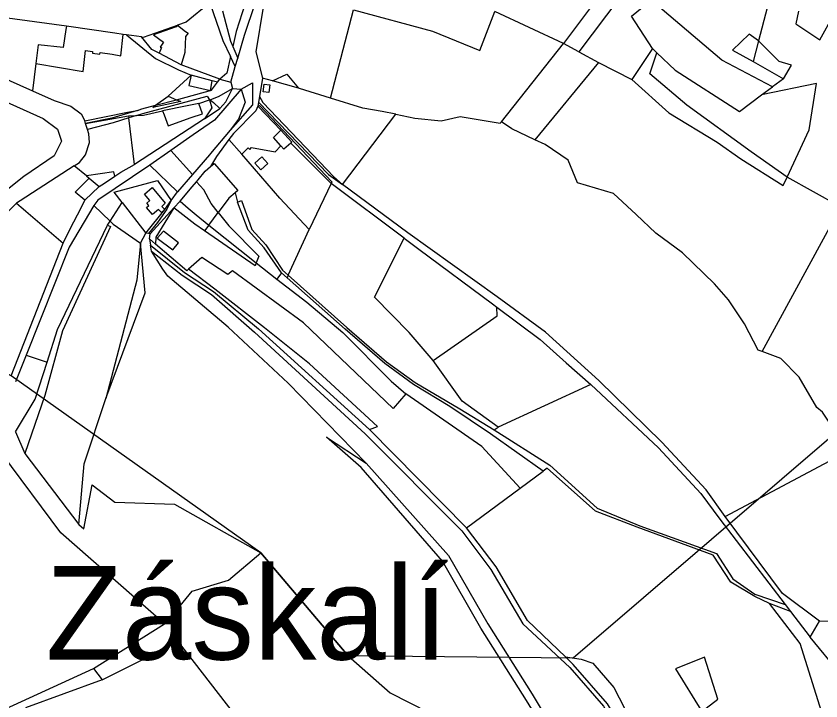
# Model space of a CAD drawing. Extents: x -689422 to -684666, y -987725 to -982160.
# Drawn here: x -687230 to -686713, y -983777 to -983338 of the extents above; entities that cross this region are included whole.
import ezdxf

# ---------------------------------------------------------------- set-up
doc = ezdxf.new("R2010")
doc.units = 0
for name, color, linetype in [('KN_Hranice_katastrální území_popis', 7, 'Continuous'), ('KN_hranice_parcel', 7, 'Continuous'), ('Migracne vyznamne uzemi', 7, 'Continuous')]:
    doc.layers.add(name, color=color, linetype=linetype)

msp = doc.modelspace()

# ---------------------------------------------------------------- linework, layer by layer
at = {"layer": 'KN_hranice_parcel'}
for p, q in [((-686834.38, -983315.81), (-686868.04, -983360.6)), ((-687105.15, -983329.15), (-687120.26, -983341.45)), ((-686746.94, -983332.27), (-686752.52, -983353.42)), ((-687027.62, -983390.28), (-687012.88, -983333.6)), ((-686877.9, -983355.22), (-686921.98, -983334.62)), ((-687120.26, -983341.45), (-687125.93, -983343.43)), ((-687158.66, -983349.73), (-687160.79, -983349.39)), ((-687149.12, -983350.91), (-687158.66, -983349.73)), ((-687087.21, -983364.63), (-687082.94, -983349.91)), ((-686752.52, -983353.42), (-686756.06, -983366.84)), ((-687090.42, -983357.15), (-687087.21, -983364.63)), ((-686917.81, -983405.46), (-686877.9, -983355.22)), ((-686868.04, -983360.6), (-686877.9, -983355.22)), ((-686820.77, -983358.38), (-686834.03, -983378.26)), ((-686817.92, -983361.09), (-686820.77, -983358.38)), ((-687184.91, -983359.69), (-687180.43, -983360.31)), ((-687123.48, -983368.86), (-687137.75, -983361.49)), ((-687088.78, -983370.02), (-687091.87, -983363.57)), ((-686868.04, -983360.6), (-686855.49, -983367.29)), ((-686817.92, -983361.09), (-686806.05, -983372.37)), ((-687259.05, -983367.72), (-687219.14, -983385.58)), ((-687216.87, -983367.98), (-687219.14, -983385.58)), ((-687098.75, -983378.01), (-687123.48, -983368.86)), ((-687088.78, -983370.02), (-687087.21, -983364.63)), ((-686855.49, -983367.29), (-686896.24, -983416.98)), ((-686855.49, -983367.29), (-686834.03, -983378.26)), ((-686756.06, -983366.84), (-686736.63, -983377.83)), ((-687125.16, -983372.16), (-687117.17, -983375.5)), ((-687091.67, -983379.99), (-687088.78, -983370.02)), ((-686806.05, -983372.37), (-686764.84, -983398.77)), ((-686736.63, -983377.83), (-686731.36, -983369.11)), ((-687117.17, -983375.5), (-687131.89, -983389.11)), ((-687103.58, -983379.2), (-687117.17, -983375.5)), ((-687100.26, -983380.11), (-687103.58, -983379.2)), ((-687100.26, -983380.11), (-687098.75, -983378.01)), ((-687098.75, -983378.01), (-687091.67, -983379.99)), ((-687071.32, -983377.38), (-687073.27, -983389.15)), ((-687064.95, -983379.22), (-687071.32, -983377.38)), ((-687048.24, -983383.9), (-687064.95, -983379.22)), ((-686736.63, -983377.83), (-686743.52, -983382.94)), ((-687091.67, -983379.99), (-687090.67, -983384.03)), ((-687090.67, -983384.03), (-687085.04, -983384.63)), ((-687047.51, -983384.13), (-687048.24, -983383.9)), ((-687027.62, -983390.28), (-687047.51, -983384.13)), ((-686750.58, -983388.18), (-686743.52, -983382.94)), ((-687219.14, -983385.58), (-687205.11, -983391.86)), ((-687140, -983394.9), (-687131.89, -983389.11)), ((-687131.89, -983389.11), (-687126.53, -983391.29)), ((-687073.27, -983389.15), (-687073.91, -983392.87)), ((-686764.84, -983398.77), (-686750.58, -983388.18)), ((-687148.74, -983397.24), (-687140, -983394.9)), ((-687123.67, -983392.46), (-687141.86, -983396.23)), ((-687141.86, -983396.23), (-687140, -983394.9)), ((-687140, -983394.9), (-687126.53, -983391.29)), ((-687126.53, -983391.29), (-687123.67, -983392.46)), ((-687112.26, -983393.83), (-687105.34, -983391.45)), ((-687105.34, -983391.45), (-687104.97, -983391.3)), ((-687077.62, -983394.49), (-687092.1, -983410.86)), ((-687073.91, -983392.87), (-687074.38, -983395.35)), ((-687006.85, -983396.7), (-687027.62, -983390.28)), ((-687151.69, -983398.13), (-687148.74, -983397.24)), ((-687108.62, -983403.55), (-687098.65, -983396.99)), ((-687059.42, -983410.87), (-687074.38, -983395.35)), ((-687184.91, -983406.49), (-687185.45, -983404.81)), ((-687184.91, -983406.49), (-687157.31, -983401.66)), ((-687157.31, -983401.66), (-687152.2, -983401.4)), ((-687157.31, -983401.66), (-687157.15, -983402.94)), ((-687152.2, -983401.4), (-687157.15, -983402.94)), ((-687153.51, -983432.98), (-687157.15, -983402.94)), ((-687108.62, -983403.55), (-687153.51, -983432.98)), ((-687019.92, -983445.77), (-686985.68, -983400.67)), ((-687183.75, -983410.33), (-687184.91, -983406.49)), ((-687089.96, -983412.96), (-687092.89, -983416.93)), ((-687092.89, -983416.93), (-687100.86, -983427.71)), ((-687084.56, -983426.38), (-687092.89, -983416.93)), ((-687027.27, -983445.21), (-687053.13, -983419.15)), ((-687130.14, -983423.89), (-687143.69, -983433.36)), ((-687116.37, -983439.4), (-687130.14, -983423.89)), ((-687084.56, -983426.38), (-687080.43, -983422.3)), ((-687100.86, -983427.71), (-687104.65, -983434.16)), ((-687192.2, -983433.83), (-687227, -983456.25)), ((-687192.2, -983433.83), (-687188.77, -983431.62)), ((-687184.47, -983440.25), (-687192.2, -983433.83)), ((-687162.32, -983437.89), (-687153.51, -983432.98)), ((-687125.91, -983450.39), (-687143.69, -983433.36)), ((-687184.47, -983440.25), (-687182.65, -983441.76)), ((-687172.88, -983444.91), (-687166.19, -983440.46)), ((-687166.19, -983440.46), (-687162.32, -983437.89)), ((-687116.37, -983439.4), (-687125.91, -983450.39)), ((-686699.86, -983460.25), (-686734.09, -983441.15)), ((-687182.65, -983441.76), (-687176.21, -983447.12)), ((-687176.21, -983447.12), (-687172.88, -983444.91)), ((-687027.27, -983445.21), (-687041.25, -983474.64)), ((-686980.35, -983480.19), (-687027.27, -983445.21)), ((-687185.36, -983455.81), (-687176.21, -983447.12)), ((-687129.91, -983455.95), (-687125.91, -983450.39)), ((-687088.86, -983451.06), (-687087.37, -983457.19)), ((-687227, -983456.25), (-687229.44, -983457.82)), ((-687128.26, -983460.84), (-687124.26, -983456.5)), ((-687229.44, -983457.82), (-687199.43, -983483.54)), ((-687179.6, -983459.23), (-687195.51, -983485.99)), ((-687179.6, -983459.23), (-687169.27, -983469.31)), ((-687169.27, -983469.31), (-687161.51, -983457.27)), ((-687161.51, -983457.27), (-687146.2, -983476.98)), ((-687128.26, -983460.84), (-687143.51, -983477.37)), ((-686750.35, -983553.02), (-686699.86, -983460.25)), ((-687105.73, -983471.87), (-687099.7, -983463.74)), ((-687170.91, -983471.86), (-687169.27, -983469.31)), ((-687169.27, -983469.31), (-687167.33, -983471.2)), ((-687167.33, -983471.2), (-687149.64, -983483.42)), ((-687105.73, -983471.87), (-687108.46, -983475.55)), ((-687105.73, -983471.87), (-687075.26, -983496.07)), ((-687149.64, -983483.42), (-687146.2, -983476.98)), ((-687144.55, -983477.22), (-687146.2, -983476.98)), ((-687143.51, -983477.37), (-687144.55, -983477.22)), ((-687143.95, -983480.62), (-687143.51, -983477.37)), ((-687054.77, -983504.1), (-687041.25, -983474.64)), ((-687140.03, -983484.01), (-687143.95, -983480.62)), ((-687143.95, -983480.62), (-687143.28, -983484.66)), ((-687232.68, -983568.74), (-687199.43, -983483.54)), ((-687195.51, -983485.99), (-687223.08, -983555.33)), ((-687142.61, -983488.68), (-687143.28, -983484.66)), ((-687075.26, -983496.07), (-687062.02, -983506.59)), ((-687059.08, -983502.58), (-687062.02, -983506.59)), ((-687055.52, -983505.74), (-687059.08, -983502.58)), ((-687054.77, -983504.1), (-687055.52, -983505.74)), ((-687018.25, -983538.77), (-687055.52, -983505.74)), ((-686750.35, -983553.02), (-686752.86, -983552.09)), ((-686738.28, -983557.47), (-686750.35, -983553.02)), ((-687223.08, -983555.33), (-687229.92, -983572.53)), ((-687223.08, -983555.33), (-687209.69, -983559.88)), ((-686860.32, -983574.25), (-686919.86, -983601.61)), ((-686922.53, -983603.39), (-686919.86, -983601.61)), ((-687229.92, -983604.69), (-687224.07, -983618.51)), ((-687002.49, -983603.13), (-686940.27, -983666.28)), ((-687224.07, -983618.51), (-687189.26, -983664.07)), ((-686774.11, -983658.97), (-686695.89, -983617.44)), ((-686905.75, -983640.73), (-686891.05, -983629.85)), ((-686940.27, -983666.28), (-686905.75, -983640.73)), ((-686732.12, -983719.97), (-686745.64, -983714.86)), ((-686735.51, -983715.55), (-686732.12, -983719.97)), ((-686732.12, -983719.97), (-686719.4, -983736.59)), ((-686876.67, -983749.23), (-686900.92, -983725.78)), ((-686713.37, -983726.29), (-686689.06, -983725.26)), ((-687179.87, -983756.72), (-687134.27, -983727.91)), ((-686719.4, -983736.59), (-686713.37, -983726.29)), ((-686647.66, -983823.83), (-686719.4, -983736.59)), ((-686871.6, -983754.13), (-686876.67, -983749.23)), ((-687245.86, -983786.78), (-687179.87, -983756.72)), ((-687179.87, -983756.72), (-687174.23, -983763.85)), ((-687174.23, -983763.85), (-687223.64, -983781.88))]:
    msp.add_line(p, q, dxfattribs=at)
for points in [[(-686871.38, -983281.58), (-686849.04, -983316.51), (-686877.9, -983355.22)], [(-687082.84, -983298.11), (-687082.36, -983329.58), (-687088.24, -983347.5), (-687090.42, -983357.15)], [(-687082.94, -983349.91), (-687076, -983329.47), (-687068.61, -983307.73), (-687064.66, -983300.02)], [(-687056.83, -983304.26), (-687070.68, -983330.55), (-687075.63, -983360.56), (-687071.32, -983377.38)], [(-686820.77, -983358.38), (-686834.14, -983337.72), (-686821.52, -983327.31)], [(-686743.52, -983382.94), (-686776.1, -983365.8), (-686821.52, -983327.31)], [(-687105.15, -983329.15), (-687096.85, -983353.17), (-687091.87, -983363.57)], [(-687197.28, -983344.02), (-687243.35, -983337.78), (-687256.96, -983337.75), (-687261.92, -983338.99), (-687267.57, -983342.89), (-687271.39, -983350.68), (-687270.61, -983356.98), (-687259.05, -983367.72)], [(-687096.9, -983334.14), (-687091.93, -983353.62), (-687090.42, -983357.15)], [(-687012.88, -983333.6), (-686962.16, -983347.24), (-686931.69, -983359.64), (-686921.98, -983334.62)], [(-686726.98, -983334.46), (-686728.61, -983342.58), (-686713.15, -983352.94), (-686704.5, -983336.92)], [(-687197.28, -983344.02), (-687197.67, -983346.12), (-687199.29, -983357.71)], [(-687160.79, -983349.39), (-687166.08, -983348.54), (-687197.28, -983344.02)], [(-687149.12, -983350.91), (-687147.83, -983351.07), (-687125.93, -983343.43)], [(-687125.93, -983343.43), (-687126.7, -983344.38), (-687134.76, -983347.23), (-687141.24, -983349.58), (-687134.81, -983354.37), (-687136.95, -983357.5), (-687136.24, -983357.83), (-687137.75, -983361.49)], [(-687125.93, -983343.43), (-687120.72, -983347.47), (-687119.15, -983348.57), (-687120.81, -983350.65), (-687121.11, -983361.01), (-687123.48, -983368.86)], [(-687180.43, -983360.31), (-687180.56, -983361.3), (-687175.81, -983361.95), (-687175.68, -983360.96), (-687167.91, -983362.03), (-687162.41, -983363.02), (-687160.79, -983349.39)], [(-687158.66, -983349.73), (-687140.02, -983364.77), (-687125.16, -983372.16)], [(-687137.75, -983361.49), (-687142.46, -983359.06), (-687149.12, -983350.91)], [(-686752.52, -983353.42), (-686758.56, -983349.29), (-686769.27, -983359.37), (-686756.06, -983366.84)], [(-686731.36, -983369.11), (-686739.22, -983366.85), (-686752.52, -983353.42)], [(-687199.29, -983357.71), (-687215.33, -983356.11), (-687216.87, -983367.98)], [(-687216.87, -983367.98), (-687186.52, -983373.22), (-687184.91, -983359.69)], [(-687091.87, -983363.57), (-687094.26, -983374.16), (-687098.75, -983378.01)], [(-686734.09, -983441.15), (-686757.39, -983424.84), (-686798.74, -983394.87), (-686822.48, -983374.58), (-686817.92, -983361.09)], [(-687268.08, -983378.32), (-687212.32, -983403.42), (-687203.07, -983410.13), (-687200.4, -983417.88), (-687205.05, -983427.44), (-687224.59, -983440.62), (-687234.11, -983448.02), (-687252.68, -983463.77)], [(-687117.17, -983375.5), (-687118.64, -983382.18), (-687104.76, -983385.4), (-687103.58, -983379.2)], [(-687064.95, -983379.22), (-687055.56, -983374.89), (-687048.24, -983383.9)], [(-686834.03, -983378.26), (-686810.31, -983399.71), (-686779.11, -983418.58), (-686763.88, -983429.25), (-686736.7, -983446.51), (-686734.09, -983441.15)], [(-687126.53, -983391.29), (-687103.99, -983385.26), (-687100.26, -983380.11)], [(-687104.97, -983391.3), (-687099.11, -983388.95), (-687090.67, -983384.03)], [(-687098.65, -983396.99), (-687094.91, -983392.71), (-687090.67, -983384.03)], [(-687085.04, -983384.63), (-687077.81, -983380.5), (-687077.62, -983394.49)], [(-687070.27, -983381.38), (-687066.66, -983381.83), (-687067.23, -983386.7), (-687070.77, -983386.25), (-687070.27, -983381.38)], [(-686734.09, -983441.15), (-686720.05, -983410.72), (-686715.43, -983380.97), (-686750.58, -983388.18)], [(-687152.2, -983401.4), (-687148.23, -983400.17), (-687106.79, -983389.12), (-687105.34, -983391.45)], [(-687085.04, -983384.63), (-687102.18, -983404.35), (-687115.8, -983413.87), (-687130.14, -983423.89)], [(-687085.04, -983384.63), (-687082.5, -983392.87), (-687086.78, -983403.8), (-687092.1, -983410.86)], [(-687073.27, -983389.15), (-687071.04, -983393.01), (-687025.45, -983440.85), (-687019.92, -983445.77)], [(-687205.11, -983391.86), (-687194.44, -983395.55), (-687187.73, -983400.36), (-687185.45, -983404.81)], [(-687135.46, -983398.48), (-687134.57, -983400.93), (-687131.99, -983407.98), (-687117.19, -983402.62), (-687109.77, -983400.29), (-687112.26, -983393.83)], [(-687112.26, -983393.83), (-687119.6, -983395.19), (-687135.46, -983398.48)], [(-687105.34, -983391.45), (-687103.94, -983396.51), (-687108.62, -983403.55)], [(-687104.97, -983391.3), (-687102.88, -983393.18), (-687098.65, -983396.99)], [(-687073.91, -983392.87), (-687028.89, -983439.35), (-687019.92, -983445.77)], [(-687185.45, -983404.81), (-687158.06, -983399.37), (-687151.69, -983398.13)], [(-687151.69, -983398.13), (-687168.16, -983403.14), (-687184.91, -983406.49)], [(-687152.2, -983401.4), (-687147.75, -983401.18), (-687135.46, -983398.48)], [(-687074.38, -983395.35), (-687075.55, -983398.42), (-687089.96, -983412.96)], [(-687074.38, -983395.35), (-687073.22, -983395.08), (-687026.67, -983443.95), (-687027.27, -983445.21)], [(-686985.68, -983400.67), (-686994.31, -983398.97), (-687006.85, -983396.7)], [(-687157.15, -983402.94), (-687167.25, -983406.07), (-687183.75, -983410.33)], [(-686985.68, -983400.67), (-686973.41, -983403.08), (-686956.48, -983404.97), (-686944.3, -983402.05), (-686918.59, -983406.45), (-686917.81, -983405.46)], [(-687188.77, -983431.62), (-687185.09, -983426.79), (-687182.46, -983418.88), (-687182.91, -983413.13), (-687183.75, -983410.33)], [(-686896.24, -983416.98), (-686911, -983409.91), (-686917.81, -983405.46)], [(-687092.1, -983410.86), (-687104.6, -983425.81), (-687105.39, -983426.75), (-687116.37, -983439.4)], [(-687059.43, -983420.94), (-687064.28, -983415.66), (-687059.42, -983410.87)], [(-687053.13, -983419.15), (-687052.49, -983418.6), (-687059.42, -983410.87)], [(-687053.13, -983419.15), (-687057.57, -983422.97), (-687059.43, -983420.94)], [(-686752.86, -983552.09), (-686761.61, -983535.35), (-686771.92, -983519.89), (-686780.95, -983509.55), (-686801.43, -983489.67), (-686818.67, -983477.06), (-686831.12, -983464.99), (-686845.86, -983451.48), (-686868.82, -983444.73), (-686874.96, -983430.17), (-686889.74, -983420.1), (-686896.24, -983416.98)], [(-687080.43, -983422.3), (-687079.52, -983423.19), (-687078.26, -983421.93)], [(-687078.26, -983421.93), (-687063.06, -983424.74), (-687059.43, -983420.94)], [(-687041.25, -983474.64), (-687060.24, -983454.53), (-687084.56, -983426.38)], [(-687072.41, -983436.39), (-687076.27, -983432.13), (-687071.69, -983427.98), (-687067.84, -983432.24), (-687072.41, -983436.39)], [(-687143.69, -983433.36), (-687177.02, -983455.88), (-687179.6, -983459.23)], [(-687113.68, -983443.99), (-687112.63, -983442.74), (-687108.05, -983437.1), (-687104.65, -983434.16)], [(-687104.65, -983434.16), (-687102.39, -983432.2), (-687087.2, -983449.61), (-687088.86, -983451.06)], [(-687166.19, -983440.46), (-687166.75, -983437.55), (-687184.47, -983440.25)], [(-687185.36, -983455.81), (-687191.66, -983450.64), (-687182.65, -983441.76)], [(-687161.51, -983457.27), (-687166.59, -983450.73), (-687138.78, -983443.09), (-687129.91, -983455.95)], [(-687124.26, -983456.5), (-687116.46, -983447.27), (-687113.68, -983443.99)], [(-687099.7, -983463.74), (-687104.21, -983458), (-687109.01, -983449.22), (-687113.68, -983443.99)], [(-686855.29, -983571.58), (-686889.43, -983540.63), (-686920.48, -983517.85), (-686977.84, -983476.82), (-687019.92, -983445.77)], [(-687134.11, -983461.78), (-687136.25, -983463.68), (-687138.03, -983461.73), (-687141.87, -983465.12), (-687145.86, -983460.64), (-687144.36, -983459.28), (-687145.56, -983457.81), (-687143.71, -983456.09), (-687147.17, -983452.07), (-687142.23, -983447.75), (-687133.82, -983457.74), (-687135.99, -983459.8), (-687134.11, -983461.78)], [(-687088.86, -983451.06), (-687092.95, -983454.63), (-687099.7, -983463.74)], [(-687199.43, -983483.54), (-687194.89, -983474.33), (-687187.86, -983460.81), (-687185.36, -983455.81)], [(-687146.2, -983476.98), (-687134.11, -983461.78), (-687129.91, -983455.95)], [(-687129.91, -983455.95), (-687132.84, -983461.59), (-687138.72, -983470.11), (-687144.55, -983477.22)], [(-687124.26, -983456.5), (-687119, -983460.9), (-687113.87, -983465.28), (-687105.73, -983471.87)], [(-687087.37, -983457.19), (-687084.69, -983456.13), (-687078.18, -983474.65), (-687069.21, -983484.42), (-687058.43, -983500.84), (-687054.77, -983504.1)], [(-687297.99, -983532.19), (-687290.25, -983531.61), (-687285.79, -983529.45), (-687278.66, -983524.7), (-687241.24, -983469.49), (-687229.44, -983457.82)], [(-687128.26, -983460.84), (-687139.78, -983479.67), (-687140.03, -983484.01)], [(-687108.46, -983475.55), (-687114.72, -983471.21), (-687128.26, -983460.84)], [(-687059.08, -983502.58), (-687070.14, -983486.44), (-687080.47, -983475.19), (-687087.37, -983457.19)], [(-687099.7, -983463.74), (-687092.92, -983472.36), (-687073.59, -983491.85), (-687075.26, -983496.07)], [(-687170.91, -983471.86), (-687168.93, -983472.74), (-687199.69, -983539.79), (-687211.12, -983581.28), (-687224.07, -983618.51)], [(-687209.69, -983559.88), (-687203.03, -983538.99), (-687170.91, -983471.86)], [(-687125.25, -983483.21), (-687134.92, -983475.68), (-687138.98, -983480.26), (-687128.99, -983487.63), (-687125.25, -983483.21)], [(-687075.26, -983496.07), (-687076.03, -983498.03), (-687108.46, -983475.55)], [(-686961.59, -983558.88), (-686977.01, -983540.76), (-686999.34, -983518.18), (-686980.35, -983480.19)], [(-686980.35, -983480.19), (-686970.82, -983487.3), (-686923.44, -983522.51), (-686920.64, -983524.61)], [(-687149.64, -983483.42), (-687152.1, -983507.27), (-687171.92, -983583.29)], [(-687171.92, -983583.29), (-687146.75, -983515.35), (-687149.64, -983483.42)], [(-687143.28, -983484.66), (-687121.38, -983502.31), (-687102.88, -983514.58)], [(-687118.75, -983500.17), (-687120.01, -983501.31), (-687140.03, -983484.01)], [(-687132.12, -983504.61), (-687135.29, -983500.21), (-687142.61, -983488.68)], [(-687142.61, -983488.68), (-687122.85, -983504.04), (-687104.01, -983516.35)], [(-686979.21, -983580.27), (-686987.29, -983589.56), (-687044.95, -983534.66), (-687090.6, -983501.22), (-687093.59, -983503.63), (-687110.37, -983492.58), (-687118.75, -983500.17)], [(-687002.49, -983603.13), (-686997.45, -983601.23), (-687041.14, -983561.02), (-687070.05, -983537.85), (-687101.88, -983513.1), (-687118.75, -983500.17)], [(-687004.71, -983624.77), (-687054.86, -983573.37), (-687093.43, -983537.39), (-687132.12, -983504.61)], [(-687062.02, -983506.59), (-687042.79, -983521.26), (-687019.67, -983540.78), (-686988.68, -983572.11), (-686979.21, -983580.27)], [(-687054.77, -983504.1), (-687017, -983537.71), (-686991.59, -983559.7), (-686973.2, -983572.97), (-686944.56, -983589.82), (-686922.53, -983603.39)], [(-687104.01, -983516.35), (-687076.53, -983540.72), (-687005.43, -983605.86), (-686943.32, -983668.14), (-686924.66, -983692.97), (-686904.1, -983727.98), (-686873.78, -983755.95), (-686852.28, -983780.95), (-686838.64, -983805.1)], [(-687102.88, -983514.58), (-687073.83, -983538.42), (-687002.49, -983603.13)], [(-686961.59, -983558.88), (-686920.62, -983530.19), (-686920.64, -983524.61)], [(-686920.64, -983524.61), (-686892.88, -983545.41), (-686876.23, -983560.26), (-686860.32, -983574.25)], [(-686891.05, -983629.85), (-686924.72, -983605.85), (-686950.97, -983588.34), (-686974.31, -983574.3), (-686992.73, -983560.74), (-687018.25, -983538.77)], [(-687229.92, -983604.69), (-687217.29, -983583.7), (-687209.69, -983559.88)], [(-686919.86, -983601.61), (-686942.95, -983584.99), (-686961.59, -983558.88)], [(-686695.8, -983607.84), (-686704.9, -983600.95), (-686707.22, -983598.51), (-686711.49, -983591.91), (-686715.23, -983588.99), (-686726.48, -983569.51), (-686738.28, -983557.47)], [(-686860.32, -983574.25), (-686816.78, -983614.9), (-686789.55, -983644.17), (-686777.54, -983660.68), (-686735.51, -983715.55)], [(-686774.11, -983658.97), (-686786.18, -983641.86), (-686814.66, -983611.34), (-686855.29, -983571.58)], [(-686905.75, -983640.73), (-686930.32, -983614.14), (-686979.21, -983580.27)], [(-687189.26, -983664.07), (-687185.82, -983625.2), (-687171.92, -983583.29)], [(-686922.53, -983603.39), (-686886.75, -983626.03), (-686856.33, -983653.57), (-686828.76, -983664.97), (-686779.57, -983682.9), (-686769, -983699.11), (-686755.02, -983708.83), (-686735.51, -983715.55)], [(-686860.35, -983856.71), (-686875.19, -983820.25), (-686901.72, -983777.23), (-686931.06, -983730.67), (-686955.61, -983687.63), (-687007.83, -983627.59), (-687030.14, -983608.06), (-687004.71, -983624.77)], [(-687134.27, -983727.91), (-687200.97, -983669.56), (-687238.68, -983618.5)], [(-687004.71, -983624.77), (-686951.7, -983684.08), (-686926.56, -983727.87), (-686898.02, -983773.11), (-686870.9, -983818.54), (-686860.35, -983856.71)], [(-686745.64, -983714.86), (-686754.97, -983710.33), (-686770.33, -983701.25), (-686781.68, -983683.89), (-686830.65, -983665.94), (-686857.35, -983655.62), (-686888.38, -983627.99), (-686891.05, -983629.85)], [(-687189.26, -983664.07), (-687186.07, -983666.92), (-687180.7, -983638.58), (-687166.07, -983649.78), (-687127.93, -983651), (-687072.27, -983682.33)], [(-686713.37, -983726.29), (-686737.08, -983708.46), (-686774.11, -983658.97)], [(-686900.92, -983725.78), (-686921.07, -983691.32), (-686940.27, -983666.28)], [(-687134.27, -983727.91), (-687126.06, -983718.85), (-687116.41, -983707.03), (-687093.23, -983699.91), (-687072.27, -983682.33)], [(-687072.27, -983682.33), (-687016.21, -983748.47), (-686989.16, -983772.22), (-686964.45, -983784.88)], [(-686653.12, -983827.06), (-686675.23, -983801.55), (-686683.02, -983812.12), (-686712.1, -983784.36), (-686725.74, -983740.53), (-686745.64, -983714.86)], [(-687174.23, -983763.85), (-687125.53, -983739.54), (-687039.51, -983850.37)], [(-686876.67, -983749.23), (-686866.53, -983750.7), (-686858.97, -983753.14), (-686845.47, -983768.96), (-686824.89, -983808.75), (-686812.98, -983834.42), (-686806.02, -983829.82), (-686799.36, -983825.4), (-686783.14, -983845.72), (-686758.86, -983829.22), (-686750.57, -983837.01), (-686775.63, -983856.45), (-686747.49, -983888.24), (-686731.43, -983879.66)], [(-686788.96, -983784.23), (-686778.81, -983776.44), (-686787.28, -983749.4), (-686805.83, -983756.81), (-686788.96, -983784.23)], [(-686835.4, -983802.79), (-686849.63, -983779.27), (-686871.6, -983754.13)]]:
    msp.add_lwpolyline(points, dxfattribs=at)
at = {"layer": 'Migracne vyznamne uzemi'}
for points in [[(-686648.64, -983558.74), (-686871.6, -983749.97), (-687016.21, -983748.47), (-687072.27, -983682.33), (-687232.68, -983568.74), (-687297.99, -983532.19), (-687310.37, -983523.82), (-687493.65, -983407.85), (-687566.18, -983356)], [(-686648.64, -983558.74), (-686871.6, -983749.97), (-687016.21, -983748.47), (-687072.27, -983682.33), (-687232.68, -983568.74), (-687297.99, -983532.19)]]:
    msp.add_lwpolyline(points, dxfattribs=at)

# ---------------------------------------------------------------- texts
at = {"layer": 'KN_Hranice_katastrální území_popis'}
msp.add_text('Záskalí', height=60, dxfattribs=at).set_placement((-687210.55, -983750.93))

doc.saveas('drawing.dxf')
